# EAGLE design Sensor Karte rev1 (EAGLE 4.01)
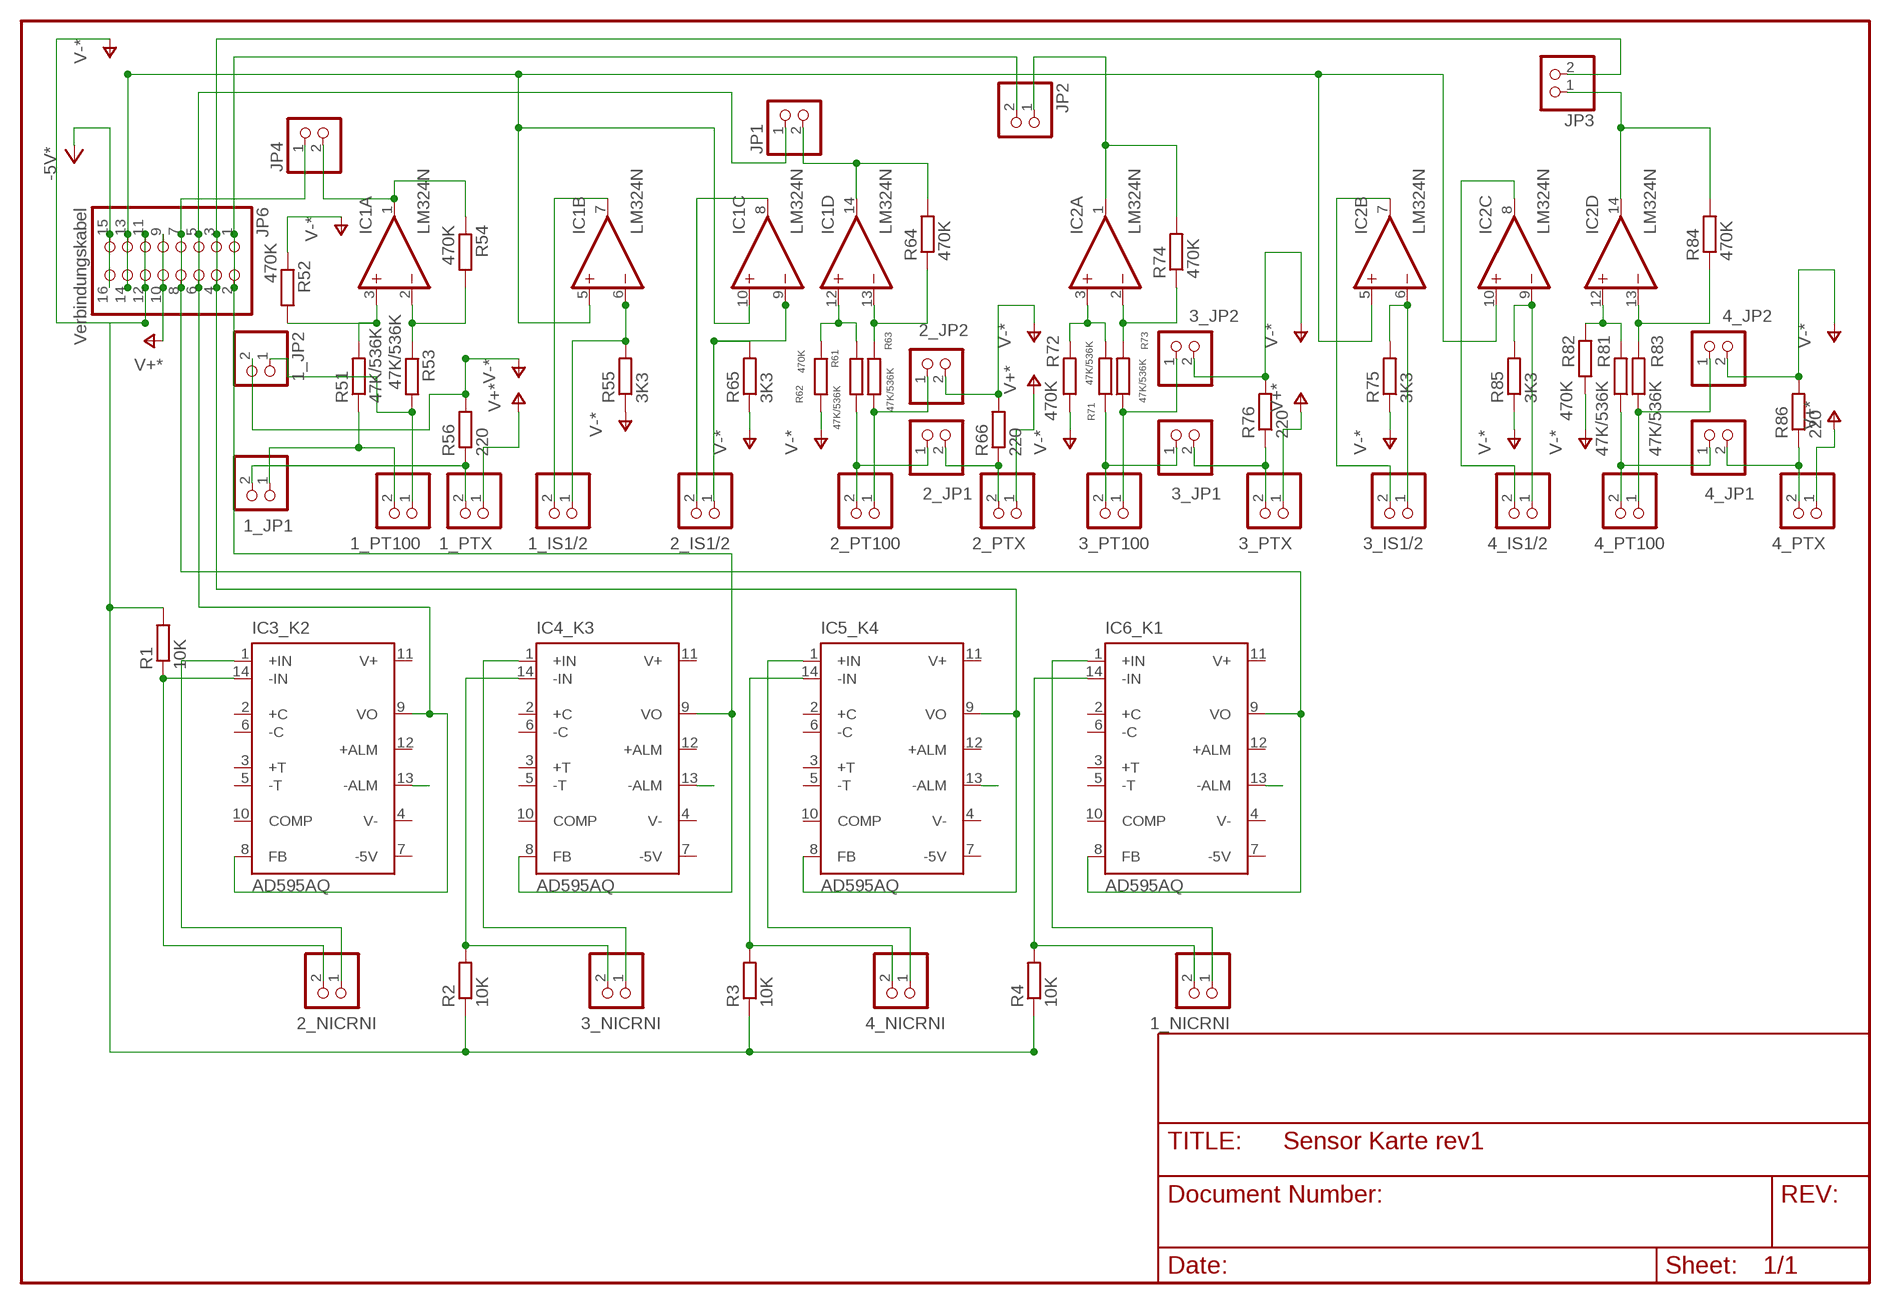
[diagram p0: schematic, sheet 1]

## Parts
1_IS1/2  PINHD-1X2  [1X02]
1_JP1  PINHD-1X2  [1X02]
1_JP2  PINHD-1X2  [1X02]
1_NICRNI  PINHD-1X2  [1X02]
1_PT100  PINHD-1X2  [1X02]
1_PTX  PINHD-1X2  [1X02]
2_IS1/2  PINHD-1X2  [1X02]
2_JP1  PINHD-1X2  [1X02]
2_JP2  PINHD-1X2  [1X02]
2_NICRNI  PINHD-1X2  [1X02]
2_PT100  PINHD-1X2  [1X02]
2_PTX  PINHD-1X2  [1X02]
3_IS1/2  PINHD-1X2  [1X02]
3_JP1  PINHD-1X2  [1X02]
3_JP2  PINHD-1X2  [1X02]
3_NICRNI  PINHD-1X2  [1X02]
3_PT100  PINHD-1X2  [1X02]
3_PTX  PINHD-1X2  [1X02]
4_IS1/2  PINHD-1X2  [1X02]
4_JP1  PINHD-1X2  [1X02]
4_JP2  PINHD-1X2  [1X02]
4_NICRNI  PINHD-1X2  [1X02]
4_PT100  PINHD-1X2  [1X02]
4_PTX  PINHD-1X2  [1X02]
IC1  LM324N  [DIL14]
IC2  LM324N  [DIL14]
IC3_K2  AD595AQ  AD595  [DIL14]
IC4_K3  AD595AQ  AD595  [DIL14]
IC5_K4  AD595AQ  AD595  [DIL14]
IC6_K1  AD595AQ  AD595  [DIL14]
JP1  PINHD-1X2  [1X02]
JP2  PINHD-1X2  [1X02]
JP3  PINHD-1X2  [1X02]
JP4  PINHD-1X2  [1X02]
JP6  Verbindungskabel  PINHD-2X8  [2X08]
R1  10K  R-EU_0204/5  [0204/5]
R2  10K  R-EU_0204/5  [0204/5]
R3  10K  R-EU_0204/7  [0204/7]
R4  10K  R-EU_0204/5  [0204/5]
R51  47K/536K  R-EU_0204/5  [0204/5]
R52  470K  R-EU_0309/12  [0309/12]
R53  47K/536K  R-EU_0204/5  [0204/5]
R54  470K  R-EU_0204/5  [0204/5]
R55  3K3  R-EU_0204/5  [0204/5]
R56  220  R-EU_0204/5  [0204/5]
R61  47K/536K  R-EU_0204/5  [0204/5]
R62  470K  R-EU_0204/5  [0204/5]
R63  47K/536K  R-EU_0204/5  [0204/5]
R64  470K  R-EU_0309/10  [0309/10]
R65  3K3  R-EU_0204/5  [0204/5]
R66  220  R-EU_0204/5  [0204/5]
R71  47K/536K  R-EU_0204/5  [0204/5]
R72  470K  R-EU_0309/10  [0309/10]
R73  47K/536K  R-EU_0204/5  [0204/5]
R74  470K  R-EU_0204/5  [0204/5]
R75  3K3  R-EU_0204/5  [0204/5]
R76  220  R-EU_0204/5  [0204/5]
R81  47K/536K  R-EU_0204/5  [0204/5]
R82  470K  R-EU_0204/5  [0204/5]
R83  47K/536K  R-EU_0204/5  [0204/5]
R84  470K  R-EU_0309/10  [0309/10]
R85  3K3  R-EU_0204/5  [0204/5]
R86  220  R-EU_0204/5  [0204/5]

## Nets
-5V: JP6.15 JP6.16 ; supply symbol labelled -5V*
COM: 1_JP2.2 2_JP2.2 3_JP2.2 4_JP2.2 JP6.11 JP6.12 R1.2 R2.1 R3.1 R4.1 R52.1 R55.1 R56.2 R62.2 R65.1 R66.2 R72.1 R75.1 R76.2 R82.1 R85.1 R86.2 ; supply symbol labelled V-*
N$1: IC1.2(A:-IN) R53.1 R54.2
N$2: 1_JP2.1 1_PT100.1 R53.2
N$3: IC1.3(A:+IN) R51.2 R52.2
N$4: 1_JP1.1 1_PT100.2 R51.1
N$5: 2_IS1/2.2 IC1.8(C:OUT)
N$6: IC1.13(D:-IN) R63.1 R64.1
N$7: 2_IS1/2.1 IC1.9(C:-IN) R65.2
N$8: 2_NICRNI.1 IC3_K2.1(+IN)
N$10: 1_JP1.2 1_PTX.2 R56.1
N$11: 1_IS1/2.2 IC1.7(B:OUT)
N$12: IC1.5(B:+IN) IC1.10(C:+IN) IC2.5(B:+IN) IC2.10(C:+IN) JP6.13 JP6.14
N$13: IC4_K3.8(FB) IC4_K3.9(VO) JP2.2 JP6.1 JP6.2
N$14: IC3_K2.8(FB) IC3_K2.9(VO) JP1.1 JP6.5 JP6.6
N$15: IC6_K1.8(FB) IC6_K1.9(VO) JP4.1 JP6.7 JP6.8
N$16: 1_IS1/2.1 IC1.6(B:-IN) R55.2
N$17: IC1.12(D:+IN) R61.1 R62.1
N$18: IC2.3(A:+IN) R71.2 R72.2
N$19: 2_JP2.1 2_PT100.1 R63.2
N$20: 2_JP1.1 2_PT100.2 R61.2
N$21: 3_IS1/2.2 IC2.7(B:OUT)
N$22: 2_JP1.2 2_PTX.2 R66.1
N$23: 3_JP1.2 3_PTX.2 R76.1
N$24: 3_JP2.1 3_PT100.1 R73.1
N$25: 3_JP1.1 3_PT100.2 R71.1
N$26: IC2.2(A:-IN) R73.2 R74.1
N$27: 3_IS1/2.1 IC2.6(B:-IN) R75.2
N$28: 4_JP1.1 4_PT100.2 R81.1
N$29: 4_JP2.1 4_PT100.1 R83.1
N$30: IC2.13(D:-IN) R83.2 R84.1
N$31: IC2.12(D:+IN) R81.2 R82.2
N$32: 3_NICRNI.2 IC4_K3.14(-IN) R2.2
N$33: IC5_K4.8(FB) IC5_K4.9(VO) JP3.2 JP6.3 JP6.4
N$34: 4_IS1/2.2 IC2.8(C:OUT)
N$35: 4_IS1/2.1 IC2.9(C:-IN) R85.2
N$36: 3_NICRNI.1 IC4_K3.1(+IN)
N$37: 4_JP1.2 4_PTX.2 R86.1
N$38: 4_NICRNI.2 IC5_K4.14(-IN) R3.2
N$39: 4_NICRNI.1 IC5_K4.1(+IN)
N$40: 1_NICRNI.2 IC6_K1.14(-IN) R4.2
N$41: 1_NICRNI.1 IC6_K1.1(+IN)
N$42: IC6_K1.13(-ALM)
N$43: IC5_K4.13(-ALM)
N$44: IC4_K3.13(-ALM)
N$45: IC3_K2.13(-ALM)
N$59: IC1.1(A:OUT) JP4.2 R54.1
N$60: 2_NICRNI.2 IC3_K2.14(-IN) R1.1
N$61: IC1.14(D:OUT) JP1.2 R64.2
N$62: IC2.14(D:OUT) JP3.1 R84.2
N$63: IC2.1(A:OUT) JP2.1 R74.2
V+: 1_PTX.1 2_PTX.1 3_PTX.1 4_PTX.1 JP6.9 JP6.10 ; supply symbol labelled V+*
Unconnected: IC3_K2.2(+C) IC3_K2.3(+T) IC3_K2.5(-T) IC3_K2.6(-C) IC3_K2.10(COMP) IC3_K2.12(+ALM) IC4_K3.2(+C) IC4_K3.3(+T) IC4_K3.5(-T) IC4_K3.6(-C) IC4_K3.10(COMP) IC4_K3.12(+ALM) IC5_K4.2(+C) IC5_K4.3(+T) IC5_K4.5(-T) IC5_K4.6(-C) IC5_K4.10(COMP) IC5_K4.12(+ALM) IC6_K1.2(+C) IC6_K1.3(+T) IC6_K1.5(-T) IC6_K1.6(-C) IC6_K1.10(COMP) IC6_K1.12(+ALM)

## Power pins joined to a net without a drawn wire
-5V: IC3_K2.7(-5V) IC4_K3.7(-5V) IC5_K4.7(-5V) IC6_K1.7(-5V)
COM: IC1.11(P:V-) IC2.11(P:V-) IC3_K2.4(V-) IC4_K3.4(V-) IC5_K4.4(V-) IC6_K1.4(V-)
V+: IC1.4(P:V+) IC2.4(P:V+) IC3_K2.11(V+) IC4_K3.11(V+) IC5_K4.11(V+) IC6_K1.11(V+)

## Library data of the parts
1_IS1/2 1_JP1 1_JP2 1_NICRNI 1_PT100 1_PTX 2_IS1/2 2_JP1 2_JP2 2_NICRNI 2_PT100 2_PTX 3_IS1/2 3_JP1 3_JP2 3_NICRNI 3_PT100 3_PTX 4_IS1/2 4_JP1 4_JP2 4_NICRNI 4_PT100 4_PTX JP1-JP4 = pinhead:PINHD-1X2: PIN HEADER
IC1 IC2 = linear:LM324N: OP AMP
IC3_K2 IC4_K3 IC5_K4 IC6_K1 = analog-devices:AD595: ANALOG DEVICES
JP6 = pinhead:PINHD-2X8: PIN HEADER
R1-R4 R51-R56 R61-R66 R71-R76 R81-R86 = rcl:R-EU_: RESISTOR, European symbol

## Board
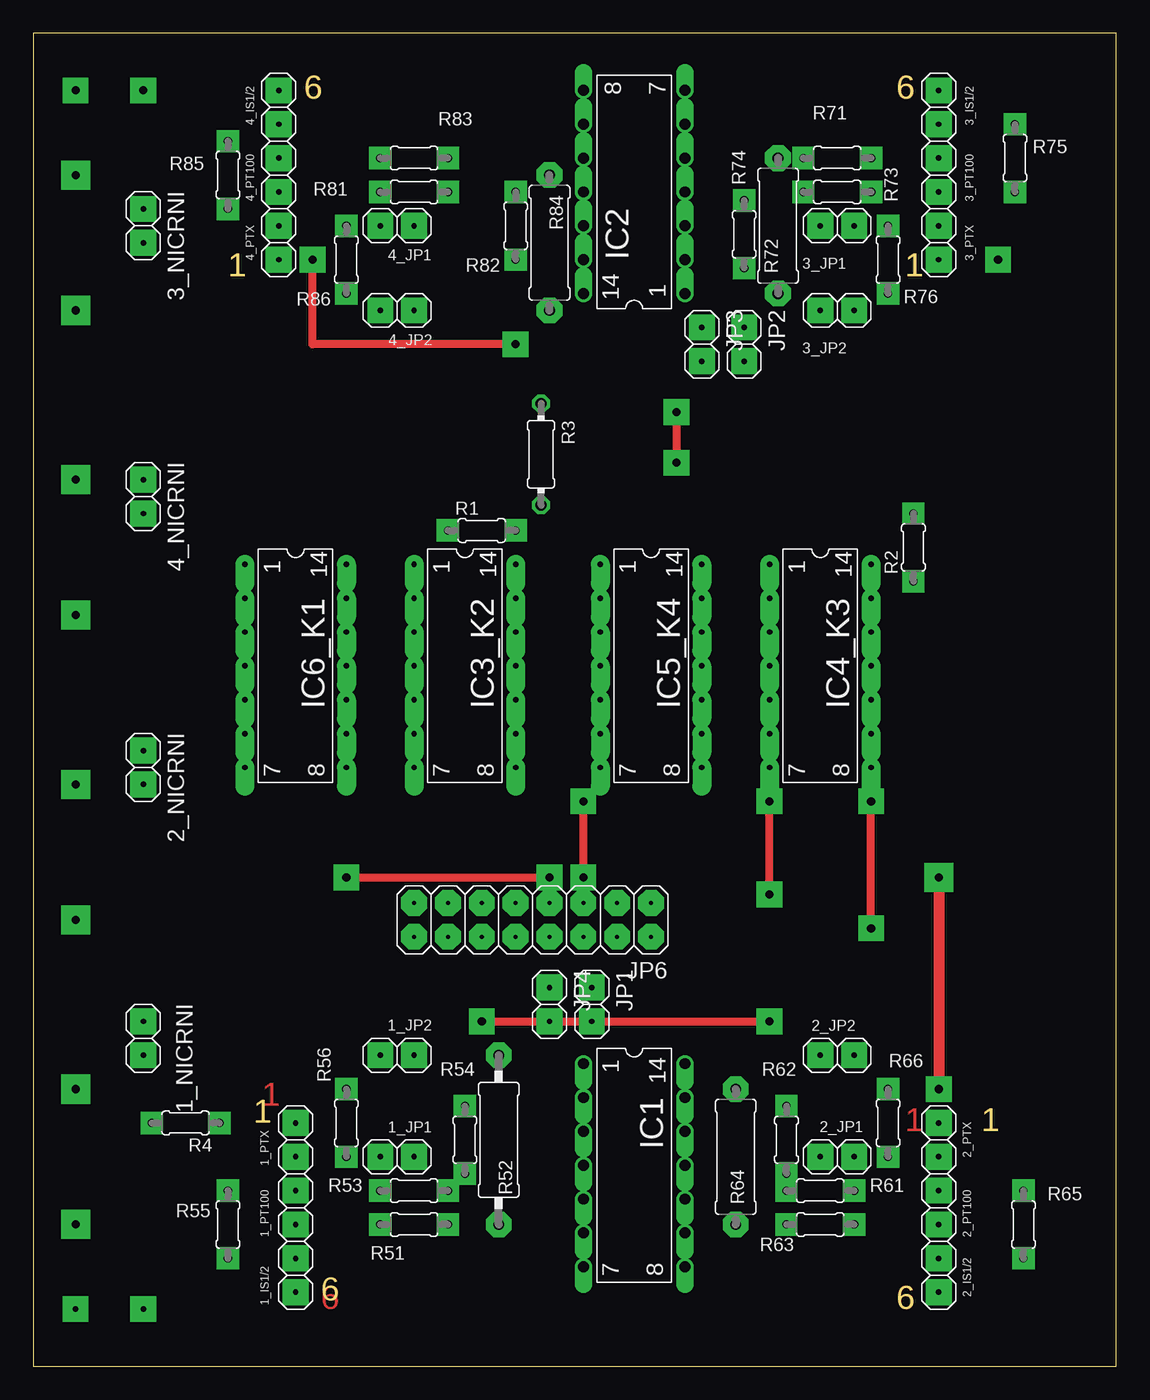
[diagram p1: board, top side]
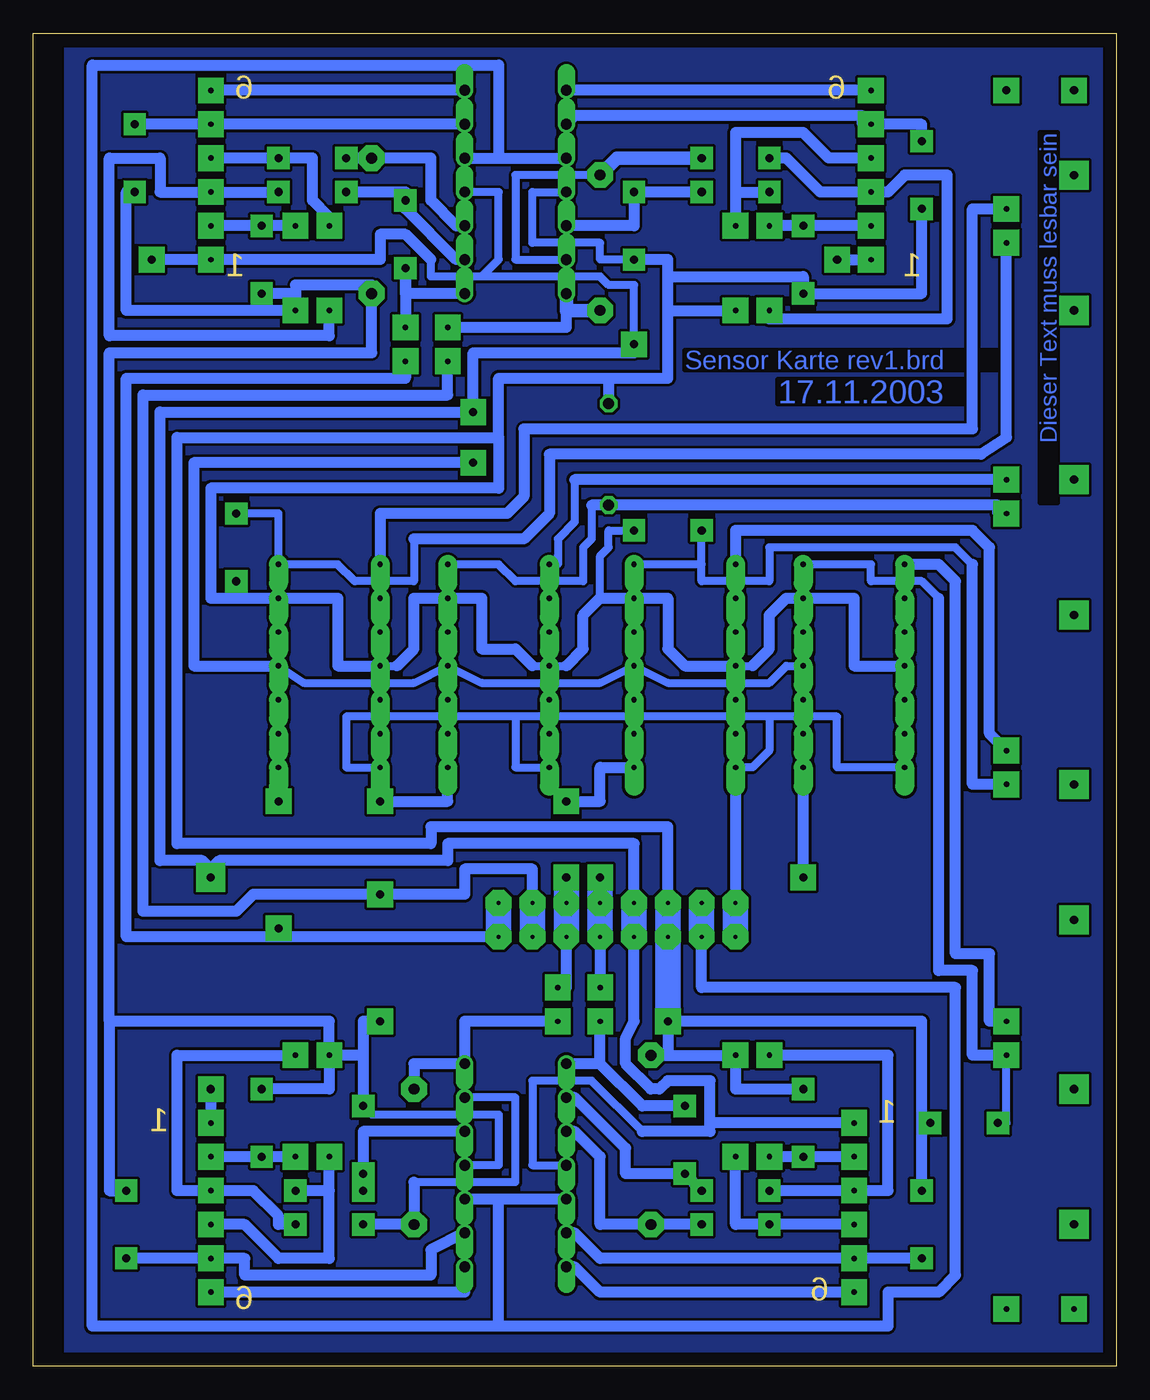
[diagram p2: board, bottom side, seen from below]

Size 81.26 x 100 mm. Coordinates in mm from the lower left corner, seen from the top.
Outline: 0,0 81.26,0 81.26,100 0,100 0,0
Copper layers used: Top, Bottom

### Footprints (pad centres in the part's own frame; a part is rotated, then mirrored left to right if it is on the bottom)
1X02 = drill 0.406 pad 1.93 square: 1 -1.27,0; 2 1.27,0
DIL14 = drill 0.813 offset: 1 -7.62,-3.81; 2 -5.08,-3.81; 3 -2.54,-3.81; 4 0,-3.81; 5 2.54,-3.81; 6 5.08,-3.81; 7 7.62,-3.81; 8 7.62,3.81; 9 5.08,3.81; 10 2.54,3.81; 11 0,3.81; 12 -2.54,3.81; 13 -5.08,3.81; 14 -7.62,3.81
DIL14' = drill 0.406 pad 1.422 offset: 1 -7.62,-3.81; 2 -5.08,-3.81; 3 -2.54,-3.81; 4 0,-3.81; 5 2.54,-3.81; 6 5.08,-3.81; 7 7.62,-3.81; 8 7.62,3.81; 9 5.08,3.81; 10 2.54,3.81; 11 0,3.81; 12 -2.54,3.81; 13 -5.08,3.81; 14 -7.62,3.81
2X08 = drill 0.305 pad 1.93 octagon: 1 -8.89,-1.27; 2 -8.89,1.27; 3 -6.35,-1.27; 4 -6.35,1.27; 5 -3.81,-1.27; 6 -3.81,1.27; 7 -1.27,-1.27; 8 -1.27,1.27; 9 1.27,-1.27; 10 1.27,1.27; 11 3.81,-1.27; 12 3.81,1.27; 13 6.35,-1.27; 14 6.35,1.27; 15 8.89,-1.27; 16 8.89,1.27
0204/5 = drill 0.61 pad 1.676 square: 1 -2.54,0; 2 2.54,0
0204/7 = drill 0.813 octagon: 1 -3.81,0; 2 3.81,0
0309/12 = drill 0.813 pad 1.93 octagon: 1 -6.35,0; 2 6.35,0
0309/10 = drill 0.813 pad 1.93 octagon: 1 -5.08,0; 2 5.08,0

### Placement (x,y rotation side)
1_IS1/2  19.68,6.82 270 top
1_JP1  27.3,15.71 180 top
1_JP2  27.3,23.33 0 top
1_NICRNI  8.25,24.6 270 top
1_PT100  19.68,11.9 270 top
1_PTX  19.68,16.98 270 top
2_IS1/2  67.94,6.82 270 top
2_JP1  60.32,15.71 0 top
2_JP2  60.32,23.33 180 top
2_NICRNI  8.25,44.92 270 top
2_PT100  67.94,11.9 270 top
2_PTX  67.94,16.98 270 top
3_IS1/2  67.94,94.45 90 top
3_JP1  60.32,85.56 0 top
3_JP2  60.32,79.21 0 top
3_NICRNI  8.25,85.56 270 top
3_PT100  67.94,89.37 90 top
3_PTX  67.94,84.29 90 top
4_IS1/2  18.41,94.45 90 top
4_JP1  27.3,85.56 180 top
4_JP2  27.3,79.21 0 top
4_NICRNI  8.25,65.24 270 top
4_PT100  18.41,89.37 90 top
4_PTX  18.41,84.29 90 top
IC1  45.08,15.08 270 top
IC2  45.08,88.1 90 top
IC3_K2  AD595AQ  [DIL14']  32.38,52.54 270 top
IC4_K3  AD595AQ  [DIL14']  59.05,52.54 270 top
IC5_K4  AD595AQ  [DIL14']  46.35,52.54 270 top
IC6_K1  AD595AQ  [DIL14']  19.68,52.54 270 top
JP1  41.91,27.14 270 top
JP2  53.34,76.67 270 top
JP3  50.16,76.67 270 top
JP4  38.73,27.14 270 top
JP6  37.46,33.49 180 top
R1  33.65,62.7 0 top
R2  66.03,61.43 90 top
R3  38.1,68.41 270 top
R4  11.43,18.25 180 top
R51  28.57,10.63 0 top
R52  34.92,16.98 270 top
R53  28.57,13.17 180 top
R54  32.38,16.98 270 top
R55  14.6,10.63 270 top
R56  23.49,18.25 90 top
R61  59.05,13.17 0 top
R62  56.51,16.98 90 top
R63  59.05,10.63 0 top
R64  52.7,15.71 90 top
R65  74.29,10.63 270 top
R66  64.13,18.25 90 top
R71  60.32,90.64 180 top
R72  55.88,85.56 90 top
R73  60.32,88.1 180 top
R74  53.34,84.92 270 top
R75  73.66,90.64 90 top
R76  64.13,83.02 270 top
R81  28.57,88.1 0 top
R82  36.19,85.56 90 top
R83  28.57,90.64 0 top
R84  38.73,84.29 270 top
R85  14.6,89.37 90 top
R86  23.49,83.02 270 top

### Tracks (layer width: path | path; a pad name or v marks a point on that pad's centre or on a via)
-5V
  Bottom 0.61: IC6_K1.7 20.95,44.92 20.95,48.73 26.03,48.73 | IC3_K2.7 27.3,44.92 26.03,46.19 26.03,48.73 | 26.03,48.73 45.08,48.73 | IC5_K4.7 45.08,44.92 45.08,48.73 | 45.08,48.73 57.78,48.73 57.78,44.92 IC4_K3.7 | JP6.16 28.57,31.58
  Bottom 0.813: IC3_K2.7 JP6.15
  Bottom 1.93: JP6.15 JP6.16
COM  (via drill 0.61 pad 1.93)
  Top 0.61: v33.65,25.87 v55.24,25.87
  Bottom 0.406: R62.2 55.88,18.88 | 33.65,23.33 R52.1
  Bottom 0.61: 3_JP2.2 61.59,80.48 | IC3_K2.4 27.3,52.54 | 41.27,52.54 IC5_K4.4 43.81,52.54 | IC4_K3.4 53.97,52.54 | IC1.11 46.35,15.08 46.35,18.88 55.88,18.88 | IC2.11 43.81,88.1 43.81,84.29 38.73,84.29 38.73,83.02 R82.1 | R1.2 38.1,62.7 38.1,61.43 38.73,60.8 38.73,57.62 | 66.03,57.62 R2.1 | R4.1 14.6,18.25 R55.1
  Bottom 0.813: R56.2 28.57,20.79 1_JP2.2 R52.1 | R55.1 14.6,25.87 v33.65,25.87 33.65,23.33 | 56.51,23.33 R62.2 | v55.24,25.87 56.51,25.87 56.51,23.33 | 56.51,23.33 2_JP2.2 | R66.2 59.05,20.79 2_JP2.2 | 75.56,25.87 59.05,25.87 2_JP2.2 | R75.1 74.29,88.1 74.29,79.21 3_JP2.2 61.59,81.11 55.88,81.11 R72.1 55.88,76.03 75.56,76.03 75.56,25.87 | 75.56,25.87 75.56,13.17 R65.1 | R85.1 14.6,80.48 R86.2 23.49,81.75 33.65,81.75 | 61.59,80.48 R76.2 | 33.65,79.21 33.65,81.75 | 33.65,79.21 4_JP2.2 | R82.1 33.65,83.02 33.65,81.75 | 46.35,69.69 70.48,69.69 70.48,39.2 51.43,39.2 51.43,40.48 33.65,40.48 JP6.11 | IC6_K1.4 19.68,52.54 19.68,57.62 24.76,57.62 26.03,56.35 26.03,53.81 27.3,52.54 | IC3_K2.4 32.38,52.54 33.65,53.81 33.65,57.62 38.73,57.62 40,56.35 40,53.81 41.27,52.54 | 43.81,52.54 45.08,53.81 47.62,53.81 47.62,57.62 52.7,57.62 52.7,53.81 53.97,52.54 | IC4_K3.4 58.41,52.54 58.41,57.62 66.03,57.62 67.94,57.62 67.94,65.88 46.35,65.88 46.35,69.69 | 46.35,69.69 46.35,74.13 38.1,74.13 | 38.1,74.13 33.65,74.13 33.65,79.21 | 38.1,74.13 R3.1
  Bottom 1.93: JP6.11 JP6.12 v33.65,25.87
N$1
  Bottom 0.813: R53.1 R54.2 36.83,14.44 36.83,16.34 40.64,20.15 IC1.2
N$2
  Bottom 0.813: 1_JP2.1 17.14,23.33 17.14,13.17 1_PT100.1 R53.2
N$3
  Bottom 0.813: R51.2 R52.2 38.73,10.63 38.73,15.71 40.64,17.61 IC1.3
N$4
  Bottom 0.813: 1_PT100.2 R51.1 28.57,10.63 1_JP1.1
N$5
  Bottom 0.813: IC1.8 48.89,5.55 2_IS1/2.2
N$6
  Bottom 0.61: IC1.13 45.08,20.15 45.08,13.81 52.7,13.81
  Bottom 0.813: 52.7,13.81 R64.1 R63.1
N$7
  Bottom 0.813: R65.2 2_IS1/2.1 65.4,8.09 65.4,6.82 51.43,6.82 51.43,8.73 IC1.9
N$8
  Bottom 0.813: IC3_K2.1 28.57,62.7 10.79,62.7 9.52,61.43 9.52,47.46 2_NICRNI.1
N$10
  Bottom 0.813: 1_PTX.2 R56.1 1_JP1.2
N$11
  Bottom 0.813: 1_IS1/2.2 38.73,5.55 40.64,7.46 IC1.7
N$12
  Bottom 0.406: 46.35,12.54 IC1.5 | 41.27,3.01 46.35,3.01 | 46.35,90.64 IC2.5
  Bottom 0.813: JP6.14 31.11,28.41 12.06,28.41 12.06,6.82 13.33,5.55 17.14,5.55 17.14,3.01 41.27,3.01 76.83,3.01 76.83,97.62 46.35,97.62 46.35,90.64 | 46.35,3.01 46.35,12.54 | IC1.5 IC1.10 | IC2.5 IC2.10
  Bottom 1.93: JP6.14 JP6.13
N$13  (via drill 0.61 pad 1.93)
  Top 0.61: v62.86,32.85 v62.86,42.38
  Bottom 0.61: JP6.2 JP6.1 | 62.86,32.22 v62.86,32.85
  Bottom 0.813: JP6.2 62.86,32.22 74.29,32.22 74.29,74.13 53.34,74.13 JP2.2 | IC4_K3.9 IC4_K3.8 v62.86,42.38
  Bottom 1.93: JP6.2 JP6.1
N$14  (via drill 0.61 pad 1.93)
  Top 0.61: v41.27,36.66 v41.27,42.38
  Bottom 0.406: JP6.6 40.64,32.22
  Bottom 0.813: IC3_K2.9 IC3_K2.8 38.73,44.92 38.73,42.38 v41.27,42.38 | JP6.6 41.27,28.41 JP1.1
  Bottom 1.93: JP6.6 JP6.5 v41.27,36.66
N$15  (via drill 0.61 pad 1.93)
  Top 0.61: v23.49,36.66 v38.73,36.66
  Bottom 0.813: IC6_K1.9 IC6_K1.8 v23.49,36.66 | JP6.8 JP4.1
  Bottom 1.93: JP6.8 JP6.7 v38.73,36.66
N$16
  Bottom 0.813: R55.2 1_IS1/2.1 38.73,8.09 40.64,10 IC1.6
N$17
  Bottom 0.813: R61.1 R62.1 56.51,17.61 IC1.12
N$18
  Bottom 0.813: R71.2 R72.2 51.43,90.64 51.43,87.47 49.53,85.56 IC2.3
N$19
  Bottom 0.813: R63.2 62.86,10.63 62.86,11.27 64.77,13.17 2_PT100.1 70.48,13.17 70.48,23.33 2_JP2.1
N$20
  Bottom 0.813: 59.05,13.17 R61.2 | 59.05,13.17 59.05,8.09 62.86,8.09 65.4,10.63 2_PT100.2 | 59.05,13.17 2_JP1.1
N$21
  Bottom 0.813: IC2.7 3_IS1/2.2
N$22
  Bottom 0.813: 2_PTX.2 R66.1 2_JP1.2
N$23
  Bottom 0.813: 3_PTX.2 R76.1 3_JP1.2
N$24
  Bottom 0.813: R73.1 3_PT100.1 71.75,88.1 71.75,90.64 75.56,90.64 75.56,77.3 59.05,77.3 3_JP2.1
N$25
  Bottom 0.813: 3_PT100.2 R71.1 60.32,90.64 60.32,87.47 59.05,86.19 3_JP1.1
N$26
  Bottom 0.813: IC2.2 49.53,83.02 53.34,86.83 R74.1 53.34,88.1 R73.2
N$27
  Bottom 0.61: 73.02,93.18 R75.2
  Bottom 0.813: 73.02,93.18 3_IS1/2.1 IC2.6
N$28
  Bottom 0.813: 28.57,88.1 4_JP1.1 | 28.57,88.1 R81.1 | 4_PT100.2 21.58,90.64 23.49,92.55 28.57,92.55 28.57,88.1
N$29
  Bottom 0.61: 26.03,78.58 4_JP2.1
  Bottom 0.813: R83.1 24.76,90.64 22.22,88.1 4_PT100.1 17.14,88.1 15.87,89.37 12.7,89.37 12.7,78.58 26.03,78.58
N$30
  Bottom 0.61: R84.1 45.08,89.37 45.08,83.02 IC2.13
  Bottom 1.016: R83.2 37.46,90.64 R84.1
N$31
  Bottom 0.813: R81.2 R82.2 36.19,85.56 IC2.12
N$32
  Bottom 0.61: 52.7,62.06 52.7,58.89 57.15,58.89 58.41,60.16 IC4_K3.14 62.86,63.97 R2.2
  Bottom 0.813: 52.7,62.06 44.45,62.06 42.54,63.97 42.54,68.41 10.16,68.41 8.25,69.69 3_NICRNI.2
N$33  (via drill 0.61 pad 1.93)
  Top 0.61: v55.24,35.39 v55.24,42.38
  Bottom 0.813: JP6.3 43.81,37.3 48.89,37.3 48.89,35.39 v55.24,35.39 64.77,35.39 66.03,34.12 73.02,34.12 73.02,72.86 50.16,72.86 JP3.2 | IC5_K4.9 IC5_K4.8 50.16,42.38 v55.24,42.38
  Bottom 1.93: JP6.4 JP6.3
N$34
  Bottom 0.813: 4_IS1/2.2 IC2.8
N$35
  Bottom 0.813: R85.2 14.6,93.18 4_IS1/2.1 19.04,93.18 19.04,93.81 40.64,93.81 IC2.9
N$36
  Bottom 0.813: IC4_K3.1 55.24,63.97 45.72,63.97 44.45,65.24 44.45,70.32 10.79,70.32 10.79,86.83 3_NICRNI.1
N$37
  Bottom 0.61: 4_PTX.2 R86.1
  Bottom 0.813: 4_JP1.2 R86.1 4_PTX.2
N$38
  Bottom 0.61: IC5_K4.14 46.35,60.16 45.08,58.89 40,58.89 40,61.43 39.37,62.06 39.37,64.61
  Bottom 0.813: 39.37,64.61 R3.2 8.89,64.61 8.89,63.97 4_NICRNI.2
N$39
  Bottom 0.61: 40.64,66.51 40.64,63.34 41.91,62.06 41.91,60.16 | 41.91,60.8 41.91,60.16 | 41.91,60.16 IC5_K4.1
  Bottom 0.813: 4_NICRNI.1 40.64,66.51
N$40
  Bottom 0.61: IC6_K1.14 18.41,60.16 18.41,58.89 14.6,58.89 13.33,57.62 | 1_NICRNI.2 8.25,18.25 R4.2
  Bottom 0.813: 1_NICRNI.2 10.79,23.33 10.79,29.68 13.33,29.68 13.33,57.62
N$41
  Bottom 0.813: IC6_K1.1 13.33,60.16 12.06,58.89 12.06,30.95 9.52,30.95 9.52,25.87 1_NICRNI.1
N$46  (via drill 0.61 pad 1.93)
  other vias: 3.17,95.72
N$47  (via drill 0.61 pad 1.93)
  other vias: 8.25,95.72
N$48  (via drill 0.41 pad 1.93)
  other vias: 8.25,4.28
N$49  (via drill 0.41 pad 1.93)
  other vias: 3.17,4.28
N$50
  pour Bottom: 1.27,98.89 0.63,98.89 0.63,0.47 78.73,0.47 78.73,98.89 0.63,98.89
N$51  (via drill 0.61 pad 2.18)
  other vias: 3.17,89.37
N$52  (via drill 0.61 pad 2.18)
  other vias: 3.17,79.21
N$53  (via drill 0.61 pad 2.18)
  other vias: 3.17,10.63
N$54  (via drill 0.61 pad 2.18)
  other vias: 3.17,20.79
N$55  (via drill 0.61 pad 2.18)
  other vias: 3.17,66.51
N$56  (via drill 0.61 pad 2.18)
  other vias: 3.17,56.35
N$57  (via drill 0.61 pad 2.18)
  other vias: 3.17,43.65
N$58  (via drill 0.61 pad 2.18)
  other vias: 3.17,33.49
N$59
  Bottom 0.813: 38.73,22.7 JP4.2 | R54.1 35.55,19.52 38.73,22.7 | 38.73,22.7 IC1.1
N$60
  Bottom 0.61: 31.11,60.16 31.11,58.89 26.03,58.89 26.03,61.43 12.06,61.43 10.79,60.16 | 31.11,60.16 IC3_K2.14 | 31.11,60.16 R1.1
  Bottom 0.813: 10.79,60.16 10.79,43.65 2_NICRNI.2
N$61
  Bottom 0.813: R64.2 52.7,22.7 IC1.14 48.89,25.87 JP1.2
N$62
  Bottom 0.813: JP3.1 41.27,77.94 41.27,79.21
  Bottom 1.016: R84.2 41.27,79.21 IC2.14
N$63
  Bottom 0.813: IC2.1 53.34,80.48 R74.2 JP2.1
V+  (via drill 0.61 pad 1.93, 0.61 pad 2.18)
  Top 0.406: v72.38,83.02 73.02,83.02
  Top 0.61: v20.95,83.02 20.95,76.67 v36.19,76.67 | v48.26,71.59 v48.26,67.78
  Top 0.813: v67.94,36.66 v67.94,20.79
  Bottom 0.406: 30.47,18.25 30.47,17.61
  Bottom 0.61: IC6_K1.11 24.76,52.54 26.03,51.27 33.65,51.27 IC3_K2.11 38.73,51.27 47.62,51.27 IC5_K4.11 52.7,51.27 60.96,51.27 IC4_K3.11 | 51.43,83.02 51.43,81.75 47.62,81.75 | 47.62,81.75 46.35,83.02 46.35,88.1 IC2.4 | 47.62,81.75 38.73,81.75 38.1,81.11 36.19,81.11 v36.19,76.67 | 35.55,17.61 39.37,21.42 43.81,21.42 43.81,15.08 IC1.4
  Bottom 0.813: v67.94,20.79 2_PTX.1 | v72.38,83.02 3_PTX.1 55.24,83.02 55.24,84.92 53.34,84.92 51.43,83.02 | v20.95,83.02 4_PTX.1 | JP6.9 36.19,39.2 50.16,39.2 50.16,37.94 67.3,37.94 67.94,37.3 | 67.94,37.3 v67.94,36.66 | 67.94,37.3 68.57,37.94 71.75,37.94 71.75,71.59 v48.26,71.59 48.26,76.03 36.19,76.03 v36.19,76.67 | IC4_K3.11 69.21,52.54 69.21,67.78 v48.26,67.78 | JP6.10 36.19,25.87 36.83,24.6 36.83,22.7 34.92,20.79 34.29,20.79 33.65,21.42 30.47,21.42 30.47,17.61 35.55,17.61 | 1_PTX.1 30.47,18.25
  Bottom 1.93: JP6.10 JP6.9

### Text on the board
Top: 6 | 6 | 1 | 1 | 1 | 1 | 6 | 6
Bottom: Dieser Text muss lesbar sein | Sensor Karte rev1.brd | 17.11.2003
Dimension: 6 | 6 | 1 | 1 | 1 | 1 | 6 | 6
